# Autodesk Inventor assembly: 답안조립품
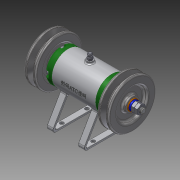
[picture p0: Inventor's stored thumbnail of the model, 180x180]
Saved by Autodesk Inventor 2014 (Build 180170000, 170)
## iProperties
Created: 2016-03
Part Number: 답안조립품
Document SubType Name: Assembly
Designer: basic
Author: basic
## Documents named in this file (15)
- C:\Users\basic\Desktop\460308V1014\답안조립품.iam
- C:\Users\basic\Desktop\460308V1014\본체.ipt
- C:\Users\basic\Desktop\460308V1014\베어링 15 x 32 x 9.ipt
- C:\Users\basic\Desktop\460308V1014\커버.ipt
- C:\Users\basic\Desktop\460308V1014\오일 실 15 25 7.ipt
- C:\Users\basic\Desktop\460308V1014\볼트 M4 x 12.ipt
- C:\Users\basic\Desktop\460308V1014\니플 M 6 x 0.75.ipt
- C:\Users\basic\Desktop\460308V1014\볼트 M 6 x 8.ipt
- C:\Users\basic\Desktop\460308V1014\와셔 6x11.5.ipt
- C:\Users\basic\Desktop\460308V1014\축.ipt
- C:\Users\basic\Desktop\460308V1014\키 3 x 3 x 12.ipt
- C:\Users\basic\Desktop\460308V1014\V벨트풀리.ipt
- C:\Users\basic\Desktop\460308V1014\와셔 8x17.ipt
- C:\Users\basic\Desktop\460308V1014\스프링와셔 8.ipt
- C:\Users\basic\Desktop\460308V1014\너트 M 8.ipt
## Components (12 placed, 3 different names)
1. KS B 2023 6002 - 15 x 32 x 9:1
2. KS B 2023 6002 - 15 x 32 x 9:2
3. V벨트풀리:1
4. V벨트풀리:2
5. ISO 4762 M4 x 12:2
6. ISO 4762 M4 x 12:3
7. ISO 4762 M4 x 12:4
8. ISO 4762 M4 x 12:5
9. ISO 4762 M4 x 12:1
10. ISO 4762 M4 x 12:6
11. ISO 4762 M4 x 12:7
12. ISO 4762 M4 x 12:8
